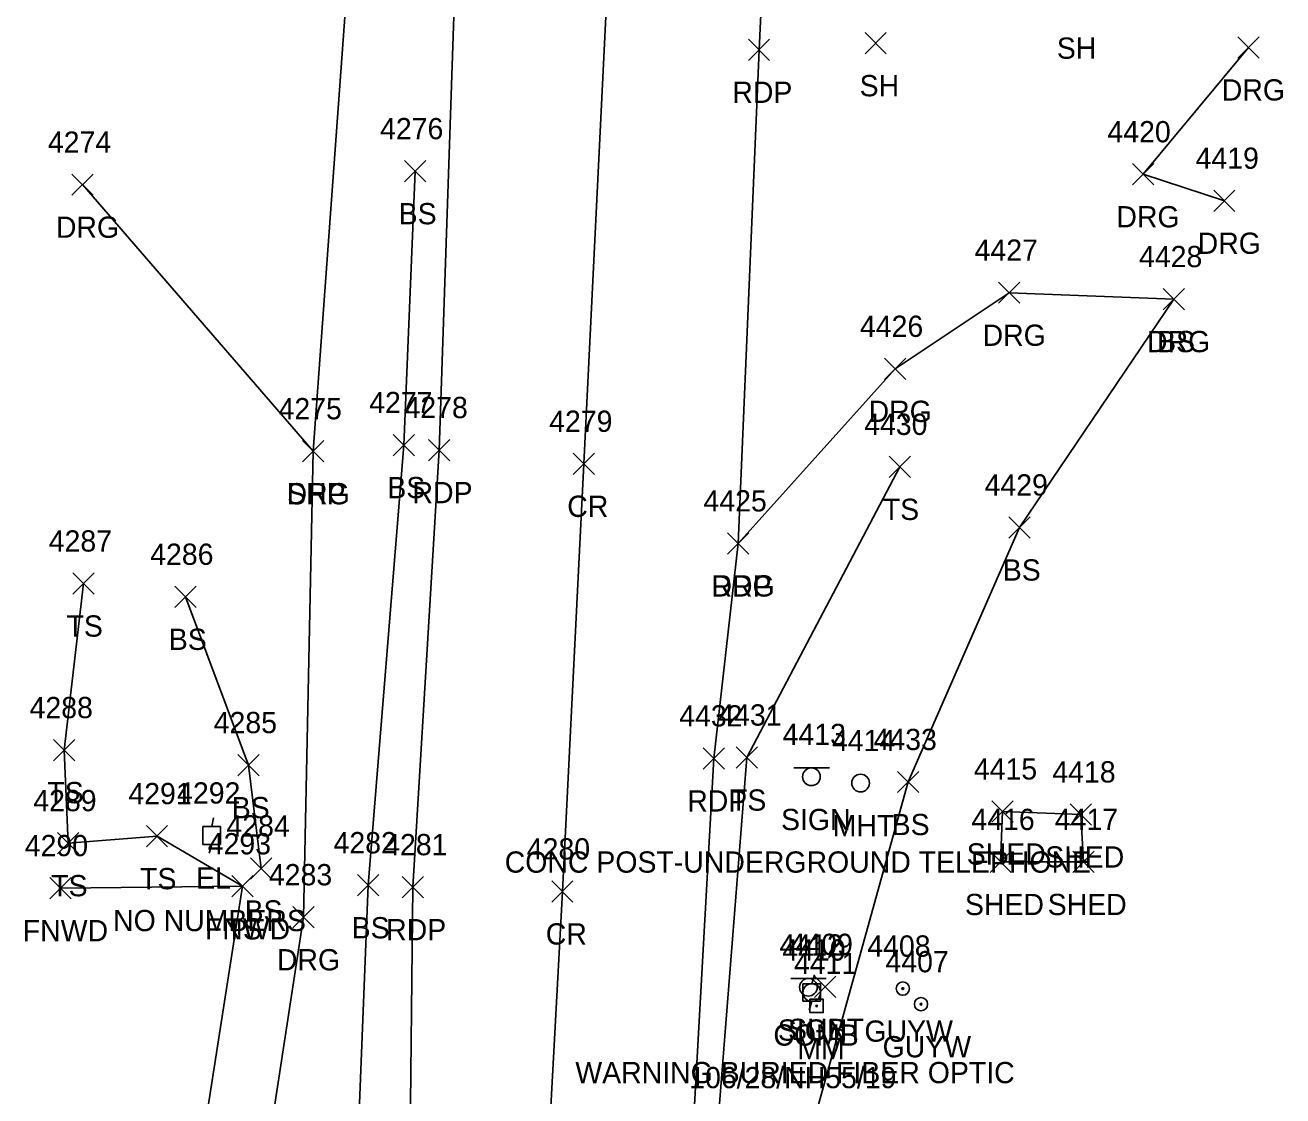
# Model space of a CAD drawing. Extents: x 1678863 to 1683592, y 407783 to 418211.
# Drawn here: x 1680252.3 to 1680370.6, y 413086.3 to 413187 of the extents above; entities that cross this region are included whole.
import ezdxf

# ---------------------------------------------------------------- set-up
doc = ezdxf.new("R2010")
doc.units = 0
for name, color, linetype in [('L_A', 7, 'Continuous'), ('L_I', 7, 'Continuous'), ('L_TIC', 7, 'Continuous'), ('LBC', 7, 'Continuous'), ('LELB', 7, 'Continuous'), ('LFNC', 7, 'Continuous'), ('P_A', 7, 'Continuous'), ('P_I', 7, 'Continuous'), ('P_TIC', 7, 'Continuous'), ('PET', 7, 'Continuous'), ('PRC', 7, 'Continuous'), ('PSP', 7, 'Continuous'), ('R_A', 7, 'Continuous'), ('R_I', 7, 'Continuous'), ('R_TIC', 7, 'Continuous'), ('RDG', 7, 'Continuous'), ('S_A', 7, 'Continuous'), ('S_C', 7, 'Continuous'), ('S_I', 7, 'Continuous'), ('SRM', 7, 'Continuous'), ('SSGN', 7, 'Continuous'), ('U_A', 7, 'Continuous'), ('U_C', 7, 'Continuous'), ('U_I', 7, 'Continuous'), ('U_TIC', 7, 'Continuous'), ('UEPT', 7, 'Continuous'), ('UP', 7, 'Continuous'), ('UPGW', 7, 'Continuous'), ('UTMH', 7, 'Continuous')]:
    doc.layers.add(name, color=color, linetype=linetype)

msp = doc.modelspace()

# ---------------------------------------------------------------- linework, layer by layer
at = {"layer": 'L_TIC'}
for points in [[(1680331.27, 413184.35), (1680333.27, 413186.35)], [(1680333.27, 413184.35), (1680331.27, 413186.35)], [(1680287.98, 413172.31), (1680289.98, 413174.31)], [(1680289.98, 413172.31), (1680287.98, 413174.31)], [(1680359.29, 413160.28), (1680361.29, 413162.28)], [(1680361.29, 413160.28), (1680359.29, 413162.28)], [(1680286.91, 413146.55), (1680288.91, 413148.55)], [(1680288.91, 413146.55), (1680286.91, 413148.55)], [(1680333.53, 413144.5), (1680335.53, 413146.5)], [(1680335.53, 413144.5), (1680333.53, 413146.5)], [(1680344.78, 413138.8), (1680346.78, 413140.8)], [(1680346.78, 413138.8), (1680344.78, 413140.8)], [(1680256.78, 413133.53), (1680258.78, 413135.53)], [(1680258.78, 413133.53), (1680256.78, 413135.53)], [(1680266.37, 413132.28), (1680268.37, 413134.28)], [(1680268.37, 413132.28), (1680266.37, 413134.28)], [(1680254.98, 413117.86), (1680256.98, 413119.86)], [(1680256.98, 413117.86), (1680254.98, 413119.86)], [(1680319.16, 413117.16), (1680321.16, 413119.16)], [(1680321.16, 413117.16), (1680319.16, 413119.16)], [(1680272.29, 413116.45), (1680274.29, 413118.45)], [(1680274.29, 413116.45), (1680272.29, 413118.45)], [(1680334.33, 413114.86), (1680336.33, 413116.86)], [(1680336.33, 413114.86), (1680334.33, 413116.86)], [(1680343.19, 413112.09), (1680345.19, 413114.09)], [(1680345.19, 413112.09), (1680343.19, 413114.09)], [(1680343.19, 413112.09), (1680345.19, 413114.09)], [(1680345.19, 413112.09), (1680343.19, 413114.09)], [(1680350.57, 413111.81), (1680352.57, 413113.81)], [(1680352.57, 413111.81), (1680350.57, 413113.81)], [(1680350.57, 413111.81), (1680352.57, 413113.81)], [(1680352.57, 413111.81), (1680350.57, 413113.81)], [(1680255.34, 413109.11), (1680257.34, 413111.11)], [(1680257.34, 413109.11), (1680255.34, 413111.11)], [(1680263.7, 413109.77), (1680265.7, 413111.77)], [(1680265.7, 413109.77), (1680263.7, 413111.77)], [(1680273.49, 413106.73), (1680275.49, 413108.73)], [(1680275.49, 413106.73), (1680273.49, 413108.73)], [(1680343.02, 413107.34), (1680345.02, 413109.34)], [(1680345.02, 413107.34), (1680343.02, 413109.34)], [(1680350.8, 413107.34), (1680352.8, 413109.34)], [(1680352.8, 413107.34), (1680350.8, 413109.34)], [(1680283.56, 413105.15), (1680285.56, 413107.15)], [(1680285.56, 413105.15), (1680283.56, 413107.15)], [(1680254.62, 413104.88), (1680256.62, 413106.88)], [(1680256.62, 413104.88), (1680254.62, 413106.88)], [(1680271.73, 413105.05), (1680273.73, 413107.05)], [(1680273.73, 413105.05), (1680271.73, 413107.05)], [(1680271.73, 413105.05), (1680273.73, 413107.05)], [(1680273.73, 413105.05), (1680271.73, 413107.05)]]:
    msp.add_lwpolyline(points, dxfattribs=at)
at = {"layer": 'LBC'}
for points in [[(1680344.19, 413113.09), (1680344.02, 413108.34), (1680351.8, 413108.34), (1680351.57, 413112.81)], [(1680344.19, 413113.09), (1680351.57, 413112.81)]]:
    msp.add_lwpolyline(points, dxfattribs=at)
at = {"layer": 'LELB'}
for points in [[(1680288.98, 413173.31), (1680287.91, 413147.55), (1680284.56, 413106.15), (1680283.11, 413069.81), (1680281.36, 413037.93), (1680281.82, 413021.58)], [(1680360.29, 413161.28), (1680345.78, 413139.8), (1680335.33, 413115.86), (1680325.49, 413080.45), (1680319.55, 413036.54), (1680322.7, 413006.17), (1680318.49, 412958.65), (1680310.76, 412916.79), (1680306.66, 412870.7), (1680302.03, 412832.78), (1680305.84, 412818.12), (1680309.53, 412807.45), (1680319.72, 412785.96), (1680342.57, 412773.22)], [(1680334.53, 413145.5), (1680320.16, 413118.16), (1680317.14, 413080.04), (1680314.23, 413037.22), (1680312.09, 413006.9), (1680310.05, 412958.33), (1680307.29, 412917.85), (1680302.46, 412870.5), (1680300, 412833.06), (1680299.33, 412809.49), (1680293.27, 412780.33), (1680285.72, 412736.77), (1680281.06, 412709.07), (1680273.24, 412667.09), (1680267.95, 412624.5), (1680272.36, 412614.56), (1680289.47, 412595.96), (1680300.87, 412585.11)], [(1680257.78, 413134.53), (1680255.98, 413118.86), (1680256.34, 413110.11), (1680264.7, 413110.77), (1680272.73, 413106.05)], [(1680274.49, 413107.73), (1680273.29, 413117.45), (1680267.37, 413133.28)]]:
    msp.add_lwpolyline(points, dxfattribs=at)
at = {"layer": 'LFNC'}
msp.add_lwpolyline([(1680255.62, 413105.88), (1680272.73, 413106.05), (1680268.67, 413079.96), (1680264.16, 413043.82), (1680260, 413027.12), (1680253.23, 413027.06)], dxfattribs=at)
at = {"layer": 'P_TIC'}
for points in [[(1680320.3, 413183.73), (1680322.3, 413185.73)], [(1680322.3, 413183.73), (1680320.3, 413185.73)], [(1680278.39, 413145.97), (1680280.39, 413147.97)], [(1680280.39, 413145.97), (1680278.39, 413147.97)], [(1680290.23, 413146.08), (1680292.23, 413148.08)], [(1680292.23, 413146.08), (1680290.23, 413148.08)], [(1680303.84, 413144.79), (1680305.84, 413146.79)], [(1680305.84, 413144.79), (1680303.84, 413146.79)], [(1680318.34, 413137.3), (1680320.34, 413139.3)], [(1680320.34, 413137.3), (1680318.34, 413139.3)], [(1680316.06, 413117.08), (1680318.06, 413119.08)], [(1680318.06, 413117.08), (1680316.06, 413119.08)], [(1680287.75, 413104.97), (1680289.75, 413106.97)], [(1680289.75, 413104.97), (1680287.75, 413106.97)], [(1680301.81, 413104.57), (1680303.81, 413106.57)], [(1680303.81, 413104.57), (1680301.81, 413106.57)]]:
    msp.add_lwpolyline(points, dxfattribs=at)
at = {"layer": 'PET'}
for points in [[(1680323.24, 413225.37), (1680321.3, 413184.73), (1680319.34, 413138.3), (1680317.06, 413118.08), (1680314.94, 413080.41), (1680312.68, 413037.4), (1680310.94, 413006.97), (1680307.94, 412957.83), (1680305.15, 412918.35), (1680300.66, 412870.52), (1680296.3, 412834.01), (1680292.92, 412809.88)], [(1680292.89, 413196.25), (1680291.23, 413147.08), (1680288.75, 413105.97), (1680288.46, 413079.82), (1680286.37, 413036.85), (1680284.95, 413018.42), (1680283.86, 412998.73), (1680281.98, 412960.23), (1680279.08, 412919.07), (1680275.8, 412880.66), (1680269.63, 412829.2), (1680265.04, 412796.13)]]:
    msp.add_lwpolyline(points, dxfattribs=at)
at = {"layer": 'PRC'}
msp.add_lwpolyline([(1680307.27, 413195.54), (1680304.84, 413145.79), (1680302.81, 413105.57), (1680301.39, 413078.93), (1680298.82, 413034.48), (1680296.98, 413005.07), (1680293.71, 412958.18), (1680291.29, 412918.89), (1680287.49, 412879.4), (1680281.38, 412827.12), (1680276.54, 412794.32)], dxfattribs=at)
at = {"layer": 'PSP'}
msp.add_lwpolyline([(1680300.43, 413398.11), (1680297.97, 413368.49), (1680294.61, 413323.14), (1680290.1, 413267.27), (1680288.79, 413239.2), (1680282.96, 413196), (1680279.39, 413146.97)], dxfattribs=at)
at = {"layer": 'R_TIC'}
for points in [[(1680366.32, 413183.95), (1680368.32, 413185.95)], [(1680368.32, 413183.95), (1680366.32, 413185.95)], [(1680356.41, 413172.02), (1680358.41, 413174.02)], [(1680358.41, 413172.02), (1680356.41, 413174.02)], [(1680256.7, 413171.04), (1680258.7, 413173.04)], [(1680258.7, 413171.04), (1680256.7, 413173.04)], [(1680364.05, 413169.53), (1680366.05, 413171.53)], [(1680366.05, 413169.53), (1680364.05, 413171.53)], [(1680343.83, 413160.88), (1680345.83, 413162.88)], [(1680345.83, 413160.88), (1680343.83, 413162.88)], [(1680359.29, 413160.28), (1680361.29, 413162.28)], [(1680361.29, 413160.28), (1680359.29, 413162.28)], [(1680333.11, 413153.72), (1680335.11, 413155.72)], [(1680335.11, 413153.72), (1680333.11, 413155.72)], [(1680278.39, 413145.97), (1680280.39, 413147.97)], [(1680280.39, 413145.97), (1680278.39, 413147.97)], [(1680318.34, 413137.3), (1680320.34, 413139.3)], [(1680320.34, 413137.3), (1680318.34, 413139.3)], [(1680277.48, 413102.14), (1680279.48, 413104.14)], [(1680279.48, 413102.14), (1680277.48, 413104.14)]]:
    msp.add_lwpolyline(points, dxfattribs=at)
at = {"layer": 'RDG'}
for points in [[(1680365.05, 413170.53), (1680357.41, 413173.02), (1680367.32, 413184.95)], [(1680257.7, 413172.04), (1680279.39, 413146.97), (1680278.48, 413103.14), (1680274.48, 413077.15), (1680268.29, 413043.19), (1680263.97, 413026.23), (1680259.53, 413011.6), (1680253.15, 413012.03)], [(1680319.34, 413138.3), (1680334.11, 413154.72), (1680344.83, 413161.88), (1680360.29, 413161.28)]]:
    msp.add_lwpolyline(points, dxfattribs=at)
at = {"layer": 'SRM'}
msp.add_lwpolyline([(1680326.09, 413095.42), (1680327.34, 413095.42), (1680327.34, 413094.17), (1680326.09, 413094.17)], close=True, dxfattribs=at)
msp.add_circle((1680326.72, 413094.79), 0.0833, dxfattribs=at)
at = {"layer": 'SSGN'}
for p, q in [((1680324.58, 413117.18), (1680327.92, 413117.18)), ((1680326.23, 413116.35), (1680326.23, 413116.35)), ((1680324.29, 413097.39), (1680327.62, 413097.39)), ((1680325.94, 413096.55), (1680325.94, 413096.55))]:
    msp.add_line(p, q, dxfattribs=at)
for centre in [(1680326.23, 413116.35), (1680325.94, 413096.55)]:
    msp.add_circle(centre, 0.833, dxfattribs=at)
at = {"layer": 'U_TIC'}
for points in [[(1680326.53, 413095.59), (1680328.53, 413097.59)], [(1680328.53, 413095.59), (1680326.53, 413097.59)]]:
    msp.add_lwpolyline(points, dxfattribs=at)
at = {"layer": 'UEPT'}
for p, q in [((1680270.01, 413112.49), (1680269.85, 413111.66)), ((1680269.01, 413109.99), (1680269.01, 413111.66)), ((1680269.01, 413111.66), (1680270.68, 413111.66)), ((1680269.85, 413110.83), (1680269.85, 413110.83)), ((1680270.68, 413111.66), (1680270.68, 413109.99)), ((1680270.68, 413109.99), (1680269.01, 413109.99)), ((1680269.6, 413109.16), (1680269.85, 413109.99))]:
    msp.add_line(p, q, dxfattribs=at)
at = {"layer": 'UP'}
for p, q in [((1680326.51, 413097.73), (1680326.26, 413096.89)), ((1680325.43, 413095.23), (1680325.43, 413096.89)), ((1680325.43, 413096.89), (1680327.09, 413096.89)), ((1680327.09, 413096.89), (1680327.09, 413095.23)), ((1680326.26, 413096.06), (1680326.26, 413096.06)), ((1680327.09, 413095.23), (1680325.43, 413095.23)), ((1680326.01, 413094.39), (1680326.26, 413095.23))]:
    msp.add_line(p, q, dxfattribs=at)
msp.add_circle((1680326.26, 413096.06), 0.833, dxfattribs=at)
at = {"layer": 'UPGW'}
for centre, radius in [((1680334.82, 413096.43), 0.625), ((1680334.82, 413096.43), 0.0833), ((1680336.53, 413094.96), 0.625), ((1680336.53, 413094.96), 0.0833)]:
    msp.add_circle(centre, radius, dxfattribs=at)
at = {"layer": 'UTMH'}
for p, q in [((1680330.85, 413115.76), (1680330.85, 413115.76)), ((1680331.69, 413115.76), (1680331.69, 413115.76))]:
    msp.add_line(p, q, dxfattribs=at)
msp.add_circle((1680330.85, 413115.76), 0.833, dxfattribs=at)

# ---------------------------------------------------------------- texts
at = {"layer": 'L_A'}
for s, p in [('SH', (1680349.3, 413183.88)), ('SH', (1680330.76, 413180.35)), ('BS', (1680287.42, 413168.31)), ('BS', (1680358.73, 413156.28)), ('BS', (1680286.35, 413142.55)), ('TS', (1680332.94, 413140.5)), ('BS', (1680344.22, 413134.8)), ('TS', (1680256.19, 413129.53)), ('BS', (1680265.81, 413128.28)), ('TS', (1680254.39, 413113.86)), ('BS', (1680271.73, 413112.45)), ('TS', (1680318.57, 413113.16)), ('BS', (1680333.77, 413110.86)), ('SHED', (1680340.83, 413108.09)), ('SHED', (1680340.83, 413108.09)), ('SHED', (1680348.21, 413107.81)), ('SHED', (1680348.21, 413107.81)), ('TS', (1680254.75, 413105.11)), ('TS', (1680263.11, 413105.77)), ('BS', (1680272.93, 413102.73)), ('SHED', (1680340.66, 413103.34)), ('SHED', (1680348.44, 413103.34)), ('FNWD', (1680252.08, 413100.88)), ('FNWD', (1680269.2, 413101.05)), ('TS', (1680271.14, 413101.05)), ('BS', (1680283, 413101.15))]:
    msp.add_text(s, height=2, dxfattribs=at).set_placement(p)
at = {"layer": 'L_I'}
for s, p in [('4276', (1680285.67, 413176.31)), ('4428', (1680357.03, 413164.28)), ('4277', (1680284.65, 413150.55)), ('4430', (1680331.19, 413148.5)), ('4429', (1680342.51, 413142.8)), ('4287', (1680254.52, 413137.53)), ('4286', (1680264.06, 413136.28)), ('4288', (1680252.72, 413121.86)), ('4285', (1680270.03, 413120.45)), ('4431', (1680317.47, 413121.16)), ('4433', (1680332.07, 413118.86)), ('4415', (1680341.5, 413116.09)), ('4415', (1680341.5, 413116.09)), ('4418', (1680348.88, 413115.81)), ('4418', (1680348.88, 413115.81)), ('4291', (1680262.01, 413113.77)), ('4289', (1680253.07, 413113.11)), ('4416', (1680341.27, 413111.34)), ('4417', (1680349.11, 413111.34)), ('4284', (1680271.23, 413110.73)), ('4290', (1680252.27, 413108.88)), ('4293', (1680269.47, 413109.05)), ('4293', (1680269.47, 413109.05)), ('4282', (1680281.3, 413109.15))]:
    msp.add_text(s, height=2, dxfattribs=at).set_placement(p)
at = {"layer": 'P_A'}
for s, p in [('RDP', (1680318.79, 413179.73)), ('SHP', (1680276.93, 413141.97)), ('RDP', (1680288.72, 413142.08)), ('CR', (1680303.27, 413140.79)), ('RDP', (1680316.83, 413133.3)), ('RDP', (1680314.55, 413113.08)), ('RDP', (1680286.24, 413100.97)), ('CR', (1680301.25, 413100.57))]:
    msp.add_text(s, height=2, dxfattribs=at).set_placement(p)
at = {"layer": 'P_I'}
for s, p in [('4275', (1680276.13, 413149.97)), ('4278', (1680287.97, 413150.08)), ('4279', (1680301.57, 413148.79)), ('4425', (1680316.08, 413141.3)), ('4432', (1680313.8, 413121.08)), ('4281', (1680286.06, 413108.97)), ('4280', (1680299.47, 413108.57))]:
    msp.add_text(s, height=2, dxfattribs=at).set_placement(p)
at = {"layer": 'R_A'}
for p in [(1680364.81, 413179.95), (1680354.9, 413168.02), (1680255.19, 413167.04), (1680362.54, 413165.53), (1680342.32, 413156.88), (1680357.78, 413156.28), (1680331.6, 413149.72), (1680276.88, 413141.97), (1680316.83, 413133.3), (1680275.97, 413098.14)]:
    msp.add_text('DRG', height=2, dxfattribs=at).set_placement(p)
at = {"layer": 'R_I'}
for s, p in [('4420', (1680354.06, 413176.02)), ('4274', (1680254.44, 413175.04)), ('4419', (1680362.35, 413173.53)), ('4427', (1680341.57, 413164.88)), ('4428', (1680357.03, 413164.28)), ('4426', (1680330.79, 413157.72)), ('4275', (1680276.13, 413149.97)), ('4425', (1680316.08, 413141.3)), ('4283', (1680275.22, 413106.14))]:
    msp.add_text(s, height=2, dxfattribs=at).set_placement(p)
at = {"layer": 'S_A'}
for s, p in [('SIGN', (1680323.37, 413111.33)), ('SIGN', (1680323.07, 413091.53)), ('MM', (1680324.9, 413089.79))]:
    msp.add_text(s, height=2, dxfattribs=at).set_placement(p)
at = {"layer": 'S_C'}
for s, p in [('CONC POST-UNDERGROUND TELEPHONE', (1680297.39, 413107.33)), ('WARNING BURIED FIBER OPTIC', (1680304.03, 413087.53))]:
    msp.add_text(s, height=2, dxfattribs=at).set_placement(p)
at = {"layer": 'S_I'}
for s, p in [('4413', (1680323.52, 413119.33)), ('4412', (1680323.22, 413099.53)), ('4411', (1680324.59, 413097.79))]:
    msp.add_text(s, height=2, dxfattribs=at).set_placement(p)
at = {"layer": 'U_A'}
for s, p in [('MHT', (1680328.23, 413110.76)), ('EL', (1680268.38, 413105.83)), ('COMB', (1680322.65, 413091.06)), ('SUBT', (1680324.03, 413091.59)), ('GUYW', (1680331.21, 413091.43)), ('GUYW', (1680332.92, 413089.96))]:
    msp.add_text(s, height=2, dxfattribs=at).set_placement(p)
at = {"layer": 'U_C'}
for s, p in [('NO NUMBERS', (1680260.57, 413101.83)), ('106/28/NH55/19', (1680314.74, 413087.06))]:
    msp.add_text(s, height=2, dxfattribs=at).set_placement(p)
at = {"layer": 'U_I'}
for s, p in [('4414', (1680328.16, 413118.76)), ('4292', (1680266.59, 413113.83)), ('4409', (1680324.18, 413099.59)), ('4408', (1680331.48, 413099.43)), ('4410', (1680323.48, 413099.06)), ('4407', (1680333.19, 413097.96))]:
    msp.add_text(s, height=2, dxfattribs=at).set_placement(p)

doc.saveas('drawing.dxf')
